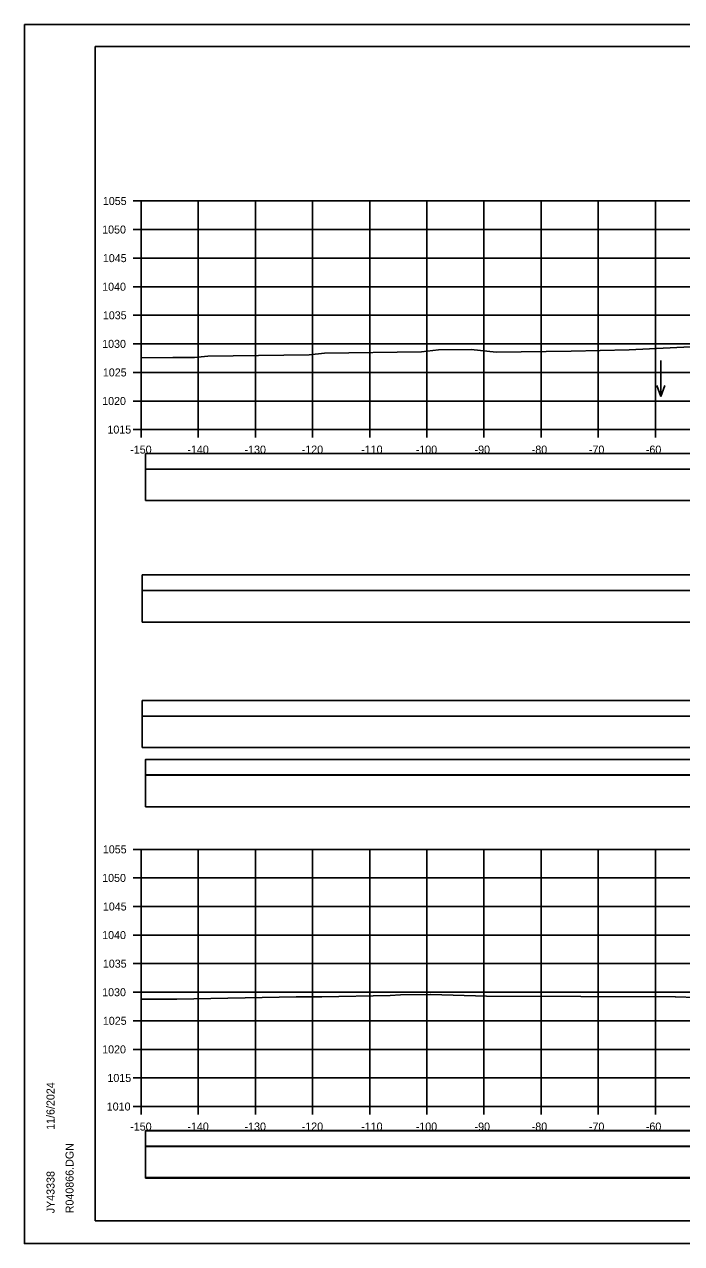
# Model space of a CAD drawing. Extents: x 1370565 to 1374448, y 301010 to 304637.
# Drawn here: x 1373198.4 to 1373313.4, y 302578.3 to 302791.7 of the extents above; entities that cross this region are included whole.
import ezdxf

# ---------------------------------------------------------------- set-up
doc = ezdxf.new("R2010")
doc.units = 0
for name, color, linetype in [('Default', 7, 'Continuous'), ('R_Axis', 7, 'Continuous'), ('R_Axis Annot', 7, 'Continuous'), ('R_Border', 7, 'Continuous'), ('R_Drive', 7, 'Continuous'), ('R_Exist Surface', 7, 'Continuous'), ('R_Grid', 7, 'Continuous'), ('R_No Plot', 7, 'Continuous'), ('R_Water Annot', 7, 'Continuous')]:
    doc.layers.add(name, color=color, linetype=linetype)

msp = doc.modelspace()

# ---------------------------------------------------------------- linework, layer by layer
at = {"layer": 'Default'}
for points in [[(1373219.61, 302660.37), (1373518.02, 302660.37), (1373518.02, 302663.07), (1373219.61, 302663.07)], [(1373219.61, 302654.79), (1373518.02, 302654.79), (1373518.02, 302660.31), (1373219.61, 302660.31)], [(1373219.61, 302595.37), (1373518.02, 302595.37), (1373518.02, 302598.07), (1373219.61, 302598.07)], [(1373219.61, 302589.79), (1373518.02, 302589.79), (1373518.02, 302595.31), (1373219.61, 302595.31)]]:
    msp.add_lwpolyline(points, close=True, dxfattribs=at)
at = {"layer": 'R_Axis'}
for p, q in [((1373217.41, 302760.78), (1373218.81, 302760.78)), ((1373218.81, 302720.78), (1373218.81, 302760.78)), ((1373217.41, 302755.78), (1373218.81, 302755.78)), ((1373217.41, 302750.78), (1373218.81, 302750.78)), ((1373217.41, 302745.78), (1373218.81, 302745.78)), ((1373217.41, 302740.78), (1373218.81, 302740.78)), ((1373217.41, 302735.78), (1373218.81, 302735.78)), ((1373217.41, 302730.78), (1373218.81, 302730.78)), ((1373217.41, 302725.78), (1373218.81, 302725.78)), ((1373217.41, 302720.78), (1373218.81, 302720.78)), ((1373218.81, 302720.78), (1373518.81, 302720.78)), ((1373218.81, 302719.38), (1373218.81, 302720.78)), ((1373228.81, 302719.38), (1373228.81, 302720.78)), ((1373238.81, 302719.38), (1373238.81, 302720.78)), ((1373248.81, 302719.38), (1373248.81, 302720.78)), ((1373258.81, 302719.38), (1373258.81, 302720.78)), ((1373268.81, 302719.38), (1373268.81, 302720.78)), ((1373278.81, 302719.38), (1373278.81, 302720.78)), ((1373288.81, 302719.38), (1373288.81, 302720.78)), ((1373298.81, 302719.38), (1373298.81, 302720.78)), ((1373308.81, 302719.38), (1373308.81, 302720.78)), ((1373217.41, 302647.33), (1373218.81, 302647.33)), ((1373218.81, 302602.33), (1373218.81, 302647.33)), ((1373217.41, 302642.33), (1373218.81, 302642.33)), ((1373217.41, 302637.33), (1373218.81, 302637.33)), ((1373217.41, 302632.33), (1373218.81, 302632.33)), ((1373217.41, 302627.33), (1373218.81, 302627.33)), ((1373217.41, 302622.33), (1373218.81, 302622.33)), ((1373217.41, 302617.33), (1373218.81, 302617.33)), ((1373217.41, 302612.33), (1373218.81, 302612.33)), ((1373217.41, 302607.33), (1373218.81, 302607.33)), ((1373217.41, 302602.33), (1373218.81, 302602.33)), ((1373218.81, 302602.33), (1373518.81, 302602.33)), ((1373218.81, 302600.93), (1373218.81, 302602.33)), ((1373228.81, 302600.93), (1373228.81, 302602.33)), ((1373238.81, 302600.93), (1373238.81, 302602.33)), ((1373248.81, 302600.93), (1373248.81, 302602.33)), ((1373258.81, 302600.93), (1373258.81, 302602.33)), ((1373268.81, 302600.93), (1373268.81, 302602.33)), ((1373278.81, 302600.93), (1373278.81, 302602.33)), ((1373288.81, 302600.93), (1373288.81, 302602.33)), ((1373298.81, 302600.93), (1373298.81, 302602.33)), ((1373308.81, 302600.93), (1373308.81, 302602.33))]:
    msp.add_line(p, q, dxfattribs=at)
at = {"layer": 'R_Border'}
for p, q in [((1373210.81, 302787.79), (1373526.99, 302787.79)), ((1373210.81, 302582.33), (1373210.81, 302787.79)), ((1373210.81, 302582.33), (1373210.81, 302582.33)), ((1373526.99, 302582.33), (1373210.81, 302582.33))]:
    msp.add_line(p, q, dxfattribs=at)
at = {"layer": 'R_Drive'}
for points in [[(1373219.61, 302713.87), (1373518.02, 302713.87), (1373518.02, 302716.58), (1373219.61, 302716.58)], [(1373219.61, 302708.35), (1373518.02, 302708.35), (1373518.02, 302713.87), (1373219.61, 302713.87)], [(1373219.02, 302692.63), (1373517.44, 302692.63), (1373517.44, 302695.34), (1373219.02, 302695.34)], [(1373219.02, 302687.11), (1373517.44, 302687.11), (1373517.44, 302692.63), (1373219.02, 302692.63)], [(1373219.02, 302670.65), (1373517.44, 302670.65), (1373517.44, 302673.35), (1373219.02, 302673.35)], [(1373219.02, 302665.13), (1373517.44, 302665.13), (1373517.44, 302670.65), (1373219.02, 302670.65)], [(1373219.61, 302595.42), (1373518.02, 302595.42), (1373518.02, 302598.13), (1373219.61, 302598.13)], [(1373219.61, 302589.9), (1373518.02, 302589.9), (1373518.02, 302595.42), (1373219.61, 302595.42)]]:
    msp.add_lwpolyline(points, close=True, dxfattribs=at)
at = {"layer": 'R_Exist Surface'}
for points in [[(1373218.81, 302733.33), (1373224.37, 302733.4), (1373228.16, 302733.42), (1373230.51, 302733.64), (1373248.24, 302733.88), (1373250.92, 302734.15), (1373267.86, 302734.4), (1373270.85, 302734.71), (1373276.59, 302734.77), (1373280.95, 302734.33), (1373294.05, 302734.51), (1373304.19, 302734.74), (1373314.95, 302735.27)], [(1373218.81, 302621.1), (1373223.77, 302621.1), (1373223.82, 302621.1), (1373223.82, 302621.1), (1373224.06, 302621.1), (1373224.13, 302621.1), (1373225.1, 302621.12), (1373245.95, 302621.51), (1373245.97, 302621.51), (1373246.01, 302621.51), (1373246.03, 302621.51), (1373250.41, 302621.52), (1373250.46, 302621.52), (1373262.38, 302621.73), (1373262.42, 302621.73), (1373264.2, 302621.85), (1373264.22, 302621.85), (1373269.47, 302621.91), (1373269.52, 302621.91), (1373279.25, 302621.66), (1373312.27, 302621.51), (1373312.29, 302621.5), (1373315.97, 302621.43)]]:
    msp.add_lwpolyline(points, dxfattribs=at)
at = {"layer": 'R_Grid'}
for p, q in [((1373218.81, 302760.78), (1373518.81, 302760.78)), ((1373218.81, 302720.78), (1373218.81, 302760.78)), ((1373228.81, 302720.78), (1373228.81, 302760.78)), ((1373238.81, 302720.78), (1373238.81, 302760.78)), ((1373248.81, 302720.78), (1373248.81, 302760.78)), ((1373258.81, 302720.78), (1373258.81, 302760.78)), ((1373268.81, 302720.78), (1373268.81, 302760.78)), ((1373278.81, 302720.78), (1373278.81, 302760.78)), ((1373288.81, 302720.78), (1373288.81, 302760.78)), ((1373298.81, 302720.78), (1373298.81, 302760.78)), ((1373308.81, 302720.78), (1373308.81, 302760.78)), ((1373218.81, 302755.78), (1373518.81, 302755.78)), ((1373218.81, 302750.78), (1373518.81, 302750.78)), ((1373218.81, 302745.78), (1373518.81, 302745.78)), ((1373218.81, 302740.78), (1373518.81, 302740.78)), ((1373218.81, 302735.78), (1373518.81, 302735.78)), ((1373218.81, 302730.78), (1373518.81, 302730.78)), ((1373218.81, 302725.78), (1373518.81, 302725.78)), ((1373218.81, 302720.78), (1373518.81, 302720.78)), ((1373218.81, 302647.33), (1373518.81, 302647.33)), ((1373228.81, 302602.33), (1373228.81, 302647.33)), ((1373238.81, 302602.33), (1373238.81, 302647.33)), ((1373248.81, 302602.33), (1373248.81, 302647.33)), ((1373258.81, 302602.33), (1373258.81, 302647.33)), ((1373268.81, 302602.33), (1373268.81, 302647.33)), ((1373278.81, 302602.33), (1373278.81, 302647.33)), ((1373288.81, 302602.33), (1373288.81, 302647.33)), ((1373298.81, 302602.33), (1373298.81, 302647.33)), ((1373308.81, 302602.33), (1373308.81, 302647.33)), ((1373218.81, 302642.33), (1373518.81, 302642.33)), ((1373218.81, 302637.33), (1373518.81, 302637.33)), ((1373218.81, 302632.33), (1373518.81, 302632.33)), ((1373218.81, 302627.33), (1373518.81, 302627.33)), ((1373218.81, 302622.33), (1373518.81, 302622.33)), ((1373218.81, 302617.33), (1373518.81, 302617.33)), ((1373218.81, 302612.33), (1373518.81, 302612.33)), ((1373218.81, 302607.33), (1373518.81, 302607.33)), ((1373218.81, 302602.33), (1373518.81, 302602.33))]:
    msp.add_line(p, q, dxfattribs=at)
at = {"layer": 'R_No Plot'}
for p, q in [((1373198.41, 302791.68), (1373531.75, 302791.68)), ((1373198.41, 302578.35), (1373531.75, 302578.35))]:
    msp.add_line(p, q, dxfattribs=at)
for points in [[(1373198.41, 302791.68), (1373531.75, 302791.68), (1373531.75, 302578.34), (1373198.41, 302578.34)], [(1373444.73, 302787.79), (1373464.35, 302787.79), (1373464.35, 302777.91), (1373480.47, 302777.91), (1373503.67, 302777.91), (1373503.67, 302753.57), (1373526.99, 302753.57), (1373526.99, 302582.33), (1373210.81, 302582.33), (1373210.81, 302787.79)]]:
    msp.add_lwpolyline(points, close=True, dxfattribs=at)
at = {"layer": 'R_Water Annot'}
for p, q in [((1373309.74, 302732.85), (1373309.74, 302726.57)), ((1373309.74, 302726.57), (1373309.05, 302728.49)), ((1373309.74, 302726.57), (1373310.42, 302728.49))]:
    msp.add_line(p, q, dxfattribs=at)

# ---------------------------------------------------------------- texts
at = {"layer": 'R_Axis Annot'}
for s, p in [('1055', (1373212.13, 302760.08)), ('1050', (1373212.01, 302755.08)), ('1045', (1373212.13, 302750.08)), ('1040', (1373212.01, 302745.08)), ('1035', (1373212.13, 302740.08)), ('1030', (1373212.01, 302735.08)), ('1025', (1373212.13, 302730.08)), ('1020', (1373212.01, 302725.08)), ('1015', (1373212.93, 302720.08)), ('-150', (1373216.92, 302716.58)), ('-140', (1373226.92, 302716.58)), ('-130', (1373236.92, 302716.58)), ('-120', (1373246.92, 302716.58)), ('-110', (1373257.32, 302716.58)), ('-100', (1373266.87, 302716.58)), ('-90', (1373277.16, 302716.58)), ('-80', (1373287.16, 302716.58)), ('-70', (1373297.16, 302716.58)), ('-60', (1373307.12, 302716.58)), ('1055', (1373212.13, 302646.63)), ('1050', (1373212.01, 302641.63)), ('1045', (1373212.13, 302636.63)), ('1040', (1373212.01, 302631.63)), ('1035', (1373212.13, 302626.63)), ('1030', (1373212.01, 302621.63)), ('1025', (1373212.13, 302616.63)), ('1020', (1373212.01, 302611.63)), ('1015', (1373212.93, 302606.63)), ('1010', (1373212.81, 302601.63)), ('-150', (1373216.92, 302598.13)), ('-140', (1373226.92, 302598.13)), ('-130', (1373236.92, 302598.13)), ('-120', (1373246.92, 302598.13)), ('-110', (1373257.32, 302598.13)), ('-100', (1373266.87, 302598.13)), ('-90', (1373277.16, 302598.13)), ('-80', (1373287.16, 302598.13)), ('-70', (1373297.16, 302598.13)), ('-60', (1373307.12, 302598.13))]:
    msp.add_text(s, height=1.4, dxfattribs=at).set_placement(p)
at = {"layer": 'R_Border'}
for s, p in [('11/6/2024', (1373203.68, 302598.25)), ('R040866.DGN', (1373207.01, 302583.65)), ('JY43338', (1373203.68, 302583.65))]:
    msp.add_text(s, height=1.4, rotation=90, dxfattribs=at).set_placement(p)

doc.saveas('drawing.dxf')
